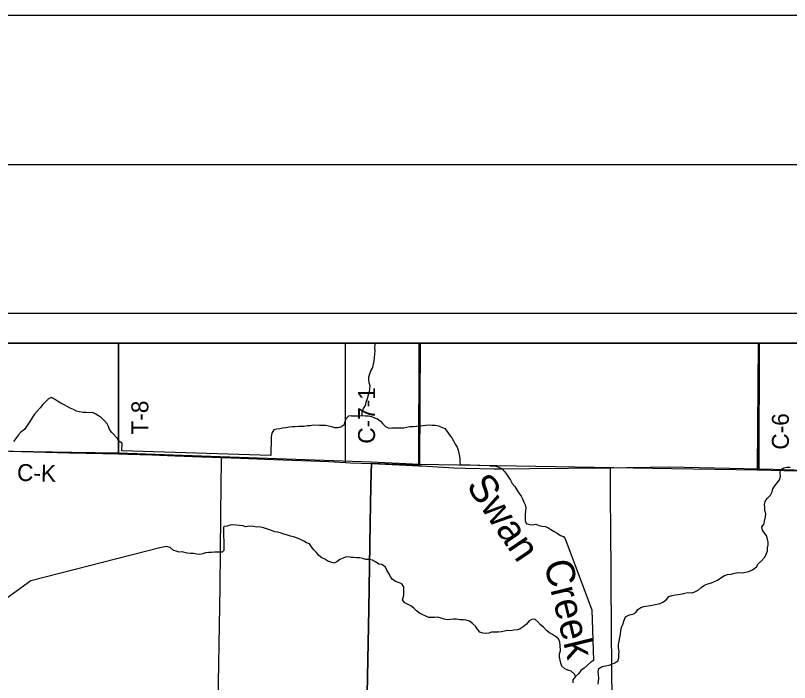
# Model space of a CAD drawing. Extents: x -21.7 to 34, y 0 to 22.
# Drawn here: x 26.522 to 29.12, y 19.76 to 22 of the extents above; entities that cross this region are included whole.
import ezdxf

# ---------------------------------------------------------------- set-up
doc = ezdxf.new("R2010")
doc.units = 0
for name, color, linetype in [('Default', 7, 'Continuous'), ('GM_X_County_Road', 7, 'Continuous'), ('GM_X_County_Road_Text', 7, 'Continuous'), ('GM_X_Interchange_Ramps', 7, 'Continuous'), ('GM_X_Minor_River', 7, 'Continuous'), ('GM_X_Minor_River_Text', 7, 'Continuous'), ('GM_X_Township_Road', 7, 'Continuous'), ('GM_X_Township_Road_Text', 7, 'Continuous'), ('SH_Border', 7, 'Continuous'), ('SH_Cut_Line', 7, 'Continuous'), ('SH_Data', 7, 'Continuous')]:
    doc.layers.add(name, color=color, linetype=linetype)

msp = doc.modelspace()

# ---------------------------------------------------------------- linework, layer by layer
at = {"layer": 'Default'}
for points in [[(26.8675, 20.9), (25.8643, 20.9), (25.8621, 20.5483), (26.7115, 20.5335), (26.8676, 20.5312)], [(27.881, 20.9), (26.8675, 20.9), (26.8676, 20.5312), (27.0512, 20.5244), (27.7165, 20.501), (27.8786, 20.4934)], [(29.0167, 20.9), (27.881, 20.9), (27.8786, 20.4934), (28.725, 20.4793), (29.0129, 20.4744)], [(30.006, 20.9), (29.0167, 20.9), (29.0129, 20.4744), (29.7259, 20.4559), (30.0077, 20.4514)]]:
    msp.add_lwpolyline(points, close=True, dxfattribs=at)
at = {"layer": 'GM_X_County_Road'}
for points in [[(27.6302, 20.4987), (27.6303, 20.5048), (27.6304, 20.5141), (27.6305, 20.5638), (27.6299, 20.741), (27.6299, 20.7658), (27.63, 20.8249), (27.6303, 20.9)], [(29.0187, 20.4775), (29.0187, 20.4852), (29.0193, 20.9)], [(26.4593, 20.5382), (26.5424, 20.5362), (26.7039, 20.5311), (26.7598, 20.5304), (26.8158, 20.5296), (26.8674, 20.5283)], [(26.8674, 20.5283), (26.8997, 20.5275), (26.9804, 20.5245), (27.0581, 20.5217), (27.1482, 20.5182), (27.2139, 20.5158)], [(27.1963, 19.5062), (27.1964, 19.5073), (27.1988, 19.5508), (27.2033, 19.7591), (27.207, 19.9519), (27.2091, 20.0793), (27.2101, 20.2006), (27.2118, 20.3219), (27.2128, 20.4245), (27.2137, 20.5022), (27.2139, 20.5158)], [(27.2139, 20.5158), (27.2786, 20.5134), (27.3594, 20.51), (27.5737, 20.5021), (27.6302, 20.4987)], [(27.6302, 20.4987), (27.6473, 20.4977), (27.717, 20.4952)], [(27.6992, 19.5006), (27.6996, 19.5488), (27.7037, 19.7788), (27.7084, 20.0054), (27.7128, 20.2943), (27.7149, 20.4186), (27.7159, 20.4621), (27.717, 20.4952)], [(27.717, 20.4952), (27.8336, 20.4902), (27.8759, 20.4883)], [(27.8759, 20.4883), (27.8864, 20.4878), (27.9573, 20.4838), (27.994, 20.4815), (28.0313, 20.48), (28.081, 20.4784), (28.1276, 20.4777), (28.1618, 20.4777), (28.2489, 20.4787), (28.507, 20.4805), (28.5189, 20.4807)], [(28.5189, 20.4807), (28.5742, 20.4817), (28.652, 20.4835), (28.7173, 20.4842), (28.7671, 20.4834), (28.9194, 20.48), (29.0187, 20.4775)], [(28.5268, 19.4873), (28.5267, 19.4976), (28.5254, 19.6466), (28.5254, 19.6682), (28.5255, 19.6736), (28.5238, 19.8343), (28.5233, 19.9152), (28.5215, 20.1238), (28.5203, 20.2794), (28.52, 20.376), (28.5193, 20.4694), (28.5191, 20.4734), (28.519, 20.4796), (28.5189, 20.4807)], [(29.0187, 20.4775), (29.0655, 20.4763), (29.2054, 20.4724), (29.2205, 20.472)]]:
    msp.add_lwpolyline(points, dxfattribs=at)
at = {"layer": 'GM_X_Interchange_Ramps'}
for points in [[(27.6994, 19.5494), (27.7034, 19.7794), (27.7082, 20.006), (27.7126, 20.2948), (27.7147, 20.4191), (27.7157, 20.4627), (27.7168, 20.4958), (27.8334, 20.4908), (27.8757, 20.4888), (27.8768, 20.9), (23.5167, 20.9)], [(30.3167, 20.9), (27.8768, 20.9), (27.8757, 20.4888), (27.8334, 20.4908), (27.7168, 20.4958), (27.7157, 20.4627), (27.7147, 20.4191), (27.7126, 20.2948), (27.7082, 20.006), (27.7034, 19.7794), (27.6994, 19.5494)]]:
    msp.add_lwpolyline(points, dxfattribs=at)
at = {"layer": 'GM_X_Minor_River'}
for points in [[(27.686, 20.6563), (27.6863, 20.6696), (27.6907, 20.6801), (27.6966, 20.6902), (27.6995, 20.702), (27.7039, 20.7144), (27.7075, 20.7265), (27.7104, 20.7367), (27.7121, 20.7469), (27.7127, 20.7564), (27.7099, 20.7667), (27.7082, 20.7773), (27.708, 20.7868), (27.7112, 20.797), (27.7148, 20.8068), (27.7215, 20.8181), (27.724, 20.8294), (27.7258, 20.8408), (27.7285, 20.8627), (27.7298, 20.8741), (27.7285, 20.884), (27.7299, 20.895), (27.7295, 20.9)], [(26.8798, 20.5638), (26.8697, 20.5708), (26.8631, 20.5805), (26.8461, 20.5998), (26.838, 20.6095), (26.8344, 20.6194), (26.8305, 20.629), (26.8212, 20.6391), (26.8112, 20.6484), (26.8011, 20.6559), (26.7914, 20.661), (26.7805, 20.6666), (26.7703, 20.666), (26.76, 20.6667), (26.7498, 20.6665), (26.7366, 20.6687), (26.7268, 20.6716), (26.717, 20.6764), (26.7061, 20.6819), (26.6956, 20.6871), (26.6855, 20.6922), (26.6743, 20.6978), (26.6634, 20.7049), (26.6534, 20.7119), (26.6432, 20.7167), (26.6336, 20.7124), (26.6236, 20.7039), (26.6142, 20.6935), (26.6049, 20.6823), (26.5951, 20.6715), (26.5858, 20.6611), (26.5791, 20.6513), (26.5724, 20.6405), (26.5661, 20.6304), (26.5597, 20.6199), (26.5527, 20.6098), (26.5407, 20.6006), (26.5314, 20.5905), (26.5231, 20.5801), (26.5157, 20.57)], [(27.6499, 20.6559), (27.6396, 20.6549), (27.6314, 20.6453), (27.6278, 20.6355), (27.6241, 20.6245), (27.6145, 20.6175), (27.6049, 20.6159), (27.5947, 20.6157), (27.5841, 20.6182), (27.5732, 20.6215), (27.5634, 20.6229), (27.5531, 20.6235), (27.5425, 20.6233), (27.5224, 20.6238), (27.5114, 20.6225), (27.5011, 20.6216), (27.4912, 20.6195), (27.4817, 20.6198), (27.4722, 20.6196), (27.4616, 20.6191), (27.4506, 20.6186), (27.4407, 20.6176), (27.43, 20.6156), (27.419, 20.614), (27.4095, 20.6119), (27.3996, 20.6113), (27.39, 20.6081), (27.3829, 20.5975), (27.3812, 20.5924), (27.38, 20.5845)], [(27.6499, 20.6559), (27.663, 20.6561), (27.6765, 20.6553), (27.686, 20.6563), (27.697, 20.6557), (27.7076, 20.6562), (27.7178, 20.653), (27.7279, 20.6486), (27.7377, 20.6457), (27.7474, 20.638), (27.7548, 20.6283), (27.7645, 20.6198), (27.7753, 20.6146), (27.7856, 20.6152), (27.7955, 20.6157), (27.8053, 20.6155), (27.8151, 20.6149), (27.8254, 20.6151), (27.836, 20.6176), (27.8459, 20.62), (27.8573, 20.6202), (27.8683, 20.6211), (27.8786, 20.622), (27.8903, 20.6233), (27.9002, 20.6239), (27.9108, 20.6255), (27.921, 20.6246), (27.9313, 20.6248), (27.9422, 20.6226), (27.9527, 20.6179), (27.9629, 20.6131), (27.9717, 20.6031), (27.978, 20.5927), (27.9868, 20.5819), (27.9923, 20.5719), (27.9985, 20.5604), (28.0044, 20.5504), (28.0084, 20.54), (28.0104, 20.5298), (28.0125, 20.5198), (28.0134, 20.5099), (28.0136, 20.5004), (28.0149, 20.4909), (28.0146, 20.4917)], [(27.38, 20.5845), (27.3789, 20.5226), (26.8796, 20.538), (26.8798, 20.5638)], [(28.1141, 20.4878), (28.0149, 20.4909)], [(28.1141, 20.4878), (28.124, 20.4876), (28.1342, 20.4866), (28.1444, 20.4834), (28.1553, 20.479), (28.1638, 20.4693), (28.17, 20.4597), (28.1766, 20.4497), (28.1836, 20.4397), (28.1891, 20.4289), (28.1984, 20.4185), (28.205, 20.4077), (28.2112, 20.3977), (28.2193, 20.3862), (28.2236, 20.3766), (28.2291, 20.3662), (28.2331, 20.3567), (28.2348, 20.3464), (28.2346, 20.3354), (28.2336, 20.3248), (28.2334, 20.3153), (28.2335, 20.3043), (28.2368, 20.2943), (28.2473, 20.2907), (28.2575, 20.2897), (28.2685, 20.2914), (28.2794, 20.2874), (28.2896, 20.2857), (28.2998, 20.2843), (28.3096, 20.2807), (28.3193, 20.274), (28.3306, 20.2677), (28.341, 20.2622), (28.3515, 20.2537), (28.3613, 20.25), (28.3679, 20.2423)], [(28.4781, 19.7541), (28.4795, 19.7643), (28.4805, 19.7749), (28.4786, 19.797), (28.4807, 19.8072), (28.4915, 19.8142), (28.5033, 19.8166), (28.5147, 19.819), (28.5242, 19.8222), (28.5345, 19.8262), (28.5441, 19.8328), (28.5474, 19.8427), (28.5476, 19.854), (28.5482, 19.8643), (28.5462, 19.8761), (28.546, 19.8875), (28.5485, 19.8988), (28.5514, 19.9113), (28.5532, 19.9227), (28.5538, 19.934), (28.557, 19.9457), (28.561, 19.9555), (28.5658, 19.9695), (28.5699, 19.9808), (28.5836, 19.987), (28.5947, 19.9902), (28.605, 19.9949), (28.6113, 20.0054), (28.6213, 20.0124), (28.6319, 20.0152), (28.6532, 20.0186), (28.6635, 20.0214), (28.6749, 20.0231), (28.6867, 20.0255), (28.6974, 20.031), (28.7074, 20.0392), (28.7156, 20.0489), (28.7266, 20.0521), (28.7365, 20.0541), (28.7468, 20.0558), (28.7597, 20.0582), (28.7692, 20.0607), (28.7791, 20.0624), (28.7924, 20.0614), (28.8027, 20.065), (28.8138, 20.0708), (28.8242, 20.079), (28.8349, 20.0871), (28.846, 20.0918), (28.8582, 20.0954), (28.8681, 20.0993), (28.8792, 20.1044), (28.8904, 20.1114), (28.9027, 20.1199), (28.9126, 20.1224), (28.9247, 20.124), (28.9361, 20.1272), (28.9487, 20.1292), (28.9616, 20.129), (28.9722, 20.131), (28.984, 20.1331), (28.9959, 20.1389), (29.0097, 20.1485), (29.0152, 20.1583), (29.026, 20.169), (29.0369, 20.1802), (29.042, 20.19), (29.046, 20.2021), (29.0466, 20.2119), (29.0483, 20.2225), (29.0485, 20.232), (29.0464, 20.2415), (29.0444, 20.2518), (29.0366, 20.2619), (29.0292, 20.2719), (29.0272, 20.2826), (29.035, 20.2927), (29.0363, 20.3025), (29.04, 20.3169), (29.0406, 20.3267), (29.0378, 20.3378), (29.038, 20.3473), (29.0363, 20.3576), (29.0392, 20.3685), (29.0458, 20.3786), (29.0566, 20.389), (29.0625, 20.4003), (29.0646, 20.4105), (29.0717, 20.4203), (29.0791, 20.4304), (29.0865, 20.4408), (29.0897, 20.4518), (29.0888, 20.4636), (29.0905, 20.4738), (29.1013, 20.4816), (29.1119, 20.4829), (29.1229, 20.4838)], [(27.6451, 20.1811), (27.6322, 20.1818), (27.6223, 20.1774), (27.6112, 20.1731), (27.6011, 20.165), (27.5915, 20.161), (27.5806, 20.1639), (27.5704, 20.1676), (27.5603, 20.1739), (27.5506, 20.1794), (27.5405, 20.1868), (27.5332, 20.1965), (27.5239, 20.2062), (27.5162, 20.2159), (27.5092, 20.2255), (27.4994, 20.2291), (27.4897, 20.2351), (27.4788, 20.2402), (27.4657, 20.2462), (27.4559, 20.2491), (27.4457, 20.252), (27.4348, 20.2553), (27.4235, 20.2586), (27.4137, 20.2614), (27.4031, 20.2647), (27.3926, 20.2661), (27.3817, 20.2705), (27.3719, 20.2741), (27.3621, 20.2774), (27.3504, 20.2807), (27.3406, 20.2824), (27.3311, 20.2823), (27.3213, 20.284), (27.3065, 20.2847), (27.2955, 20.2834), (27.2849, 20.2859), (27.2739, 20.2873), (27.2626, 20.2887), (27.2523, 20.2893), (27.2424, 20.288), (27.2329, 20.2856), (27.2225, 20.2837), (27.2211, 20.2832)], [(27.223, 20.2046), (27.2211, 20.2832)], [(28.3679, 20.2423), (28.4571, 20.0043), (28.462, 19.8341)], [(27.223, 20.2046), (27.2164, 20.1978), (27.2012, 20.1979), (27.1902, 20.1977), (27.1803, 20.1968), (27.1709, 20.197), (27.1606, 20.1953), (27.151, 20.1921), (27.1415, 20.1905), (27.1309, 20.1907), (27.1195, 20.1929), (27.1097, 20.1935), (27.0987, 20.1948), (27.0817, 20.1986), (27.0722, 20.1981), (27.0621, 20.2013), (27.0523, 20.2035), (27.0419, 20.2134), (27.0292, 20.2174), (27.0073, 20.2124)], [(27.0073, 20.2124), (26.5737, 20.1018)], [(28.4021, 19.7799), (28.3985, 19.7887), (28.3873, 19.798), (28.3761, 19.8021), (28.3663, 19.8064), (28.3566, 19.8146), (28.353, 19.8249), (28.3481, 19.8455), (28.348, 19.8565), (28.3512, 19.8664), (28.3509, 19.8861), (28.3495, 19.8956), (28.3448, 19.9071), (28.3348, 19.9149), (28.3251, 19.9219), (28.3153, 19.9267), (28.3049, 19.9353), (28.2941, 19.9461), (28.2844, 19.9535), (28.2751, 19.9636), (28.2655, 19.9725), (28.2556, 19.9719), (28.246, 19.9668), (28.2371, 19.9556), (28.2263, 19.9467), (28.2167, 19.9408), (28.2068, 19.9376), (28.1954, 19.9359), (28.1855, 19.9342), (28.1745, 19.9345), (28.1639, 19.9328), (28.1532, 19.9307), (28.143, 19.9298), (28.1316, 19.9296), (28.1206, 19.9287), (28.1107, 19.9263), (28.1012, 19.9253), (28.0914, 19.9255), (28.0809, 19.9291), (28.0731, 19.9388), (28.0661, 19.9492), (28.0568, 19.9589), (28.0464, 19.9659), (28.0351, 19.9696), (28.0252, 19.9705), (28.0139, 19.9711), (28.0025, 19.9725), (27.992, 19.9731), (27.9821, 19.9721), (27.9726, 19.9708), (27.9616, 19.9726), (27.9507, 19.9766), (27.9398, 19.9791), (27.9292, 19.9785), (27.9193, 19.9783), (27.9095, 19.9785), (27.8993, 19.9829), (27.8896, 19.9869), (27.8787, 19.9932), (27.8679, 20.0006), (27.8593, 20.0103), (27.8496, 20.0173), (27.8399, 20.0217), (27.8294, 20.028), (27.8213, 20.0377), (27.8254, 20.0528), (27.8255, 20.0622), (27.8261, 20.0717), (27.8256, 20.0812), (27.8189, 20.0912), (27.8077, 20.096), (27.7979, 20.0996), (27.787, 20.1067), (27.7816, 20.1163), (27.7757, 20.1267), (27.7687, 20.1371), (27.764, 20.1478), (27.7524, 20.156), (27.7415, 20.1574), (27.7303, 20.1652), (27.7205, 20.1714), (27.7107, 20.1732), (27.6986, 20.1734), (27.6881, 20.1767), (27.6783, 20.1788), (27.6673, 20.179), (27.6574, 20.1796), (27.6489, 20.1803), (27.6451, 20.1811)], [(26.5737, 20.1018), (26.4463, 20.0101), (26.3229, 20.0053), (26.3163, 20.0013), (26.3146, 19.9934), (26.3128, 19.9801), (26.3104, 19.9745), (26.302, 19.9712), (26.2578, 19.9665)], [(28.462, 19.8341), (28.4523, 19.8275), (28.4419, 19.819), (28.4307, 19.8082), (28.4203, 19.8), (28.4126, 19.7899), (28.4021, 19.7799), (28.3936, 19.7694), (28.393, 19.7592)]]:
    msp.add_lwpolyline(points, dxfattribs=at)
at = {"layer": 'GM_X_Township_Road'}
msp.add_lwpolyline([(26.8674, 20.5283), (26.8675, 20.5359), (26.8693, 20.6105), (26.8695, 20.6447), (26.8694, 20.9)], dxfattribs=at)
at = {"layer": 'SH_Border'}
msp.add_lwpolyline([(1.5, 21.5), (33.5, 21.5), (33.5, 0.5), (1.5, 0.5)], close=True, dxfattribs=at)
at = {"layer": 'SH_Cut_Line'}
msp.add_lwpolyline([(0, 0), (34, 0), (34, 22), (0, 22)], close=True, dxfattribs=at)
at = {"layer": 'SH_Data'}
msp.add_line((23.5167, 20.9), (30.3167, 20.9), dxfattribs=at)
for points in [[(23.4167, 21), (30.4167, 21), (30.4167, 14), (23.4167, 14)], [(23.5167, 20.9), (30.3167, 20.9), (30.3167, 14.1), (23.5167, 14.1)]]:
    msp.add_lwpolyline(points, close=True, dxfattribs=at)

# ---------------------------------------------------------------- texts
at = {"layer": 'GM_X_County_Road_Text'}
for s, rotation, p in [('C-7-1', 90, (27.7291, 20.562)), ('C-6', 90, (29.1182, 20.542)), ('C-K', 358.4097, (26.5268, 20.4375))]:
    msp.add_text(s, height=0.05682, rotation=rotation, dxfattribs=at).set_placement(p)
at = {"layer": 'GM_X_Minor_River_Text'}
for s, rotation, p in [('Swan', 303.9533, (28.0332, 20.4208)), ('Creek', 283.7207, (28.2956, 20.1617))]:
    msp.add_text(s, height=0.09476, rotation=rotation, dxfattribs=at).set_placement(p)
at = {"layer": 'GM_X_Township_Road_Text'}
msp.add_text('T-8', height=0.05682, rotation=90, dxfattribs=at).set_placement((26.9681, 20.5928))

doc.saveas('drawing.dxf')
